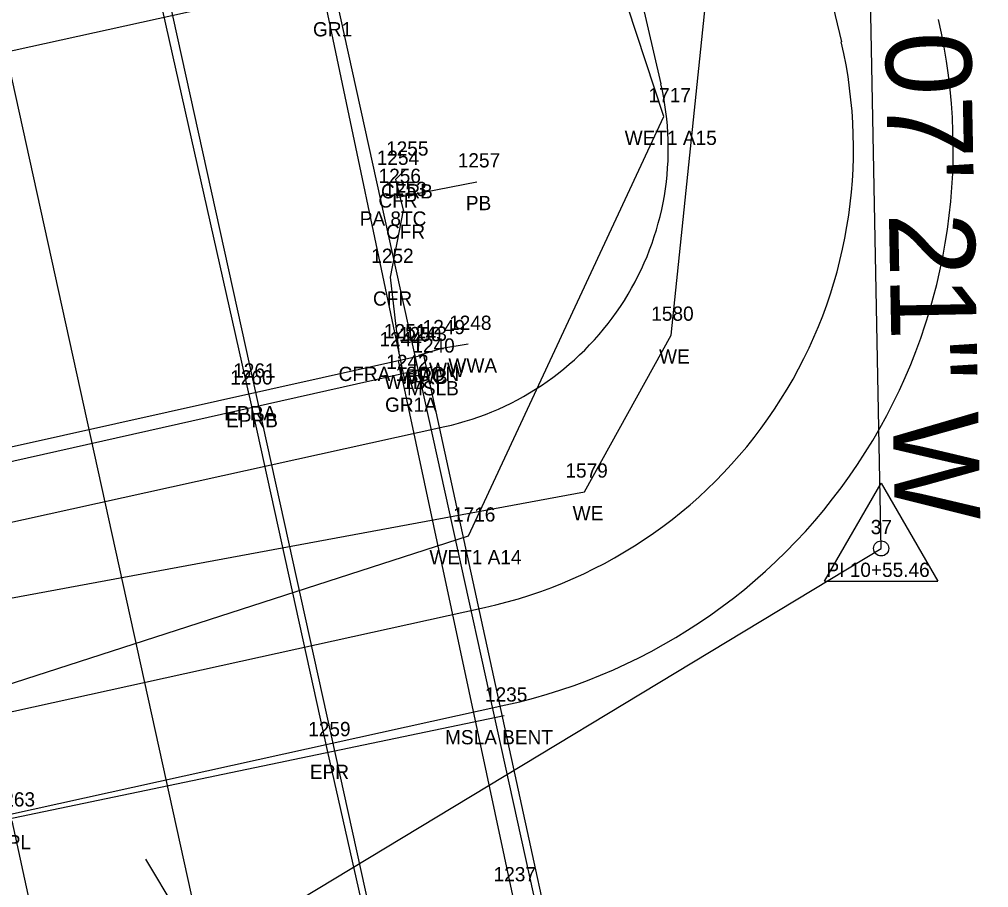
# Model space of a CAD drawing. Extents: x 2521558 to 2524785, y 882711 to 887632.
# Drawn here: x 2523776.7 to 2523844.7, y 885124.5 to 885185.4 of the extents above; entities that cross this region are included whole.
import ezdxf

# ---------------------------------------------------------------- set-up
doc = ezdxf.new("R2010")
doc.units = 0
for name, color, linetype in [('RD_EV_JW', 7, 'Continuous'), ('RD_EX_BldgApp', 7, 'Continuous'), ('RD_EX_BldgApp_txCode', 7, 'Continuous'), ('RD_EX_Bridge', 7, 'Continuous'), ('RD_EX_Bridge_txCode', 7, 'Continuous'), ('RD_EX_Conc', 7, 'Continuous'), ('RD_EX_Conc_txCode', 7, 'Continuous'), ('RD_EX_DR_Pipe', 7, 'Continuous'), ('RD_EX_DR_Pipe_txCode', 7, 'Continuous'), ('RD_EX_GuardRail', 7, 'Continuous'), ('RD_EX_GuardRail_txCode', 7, 'Continuous'), ('RD_EX_H2O', 7, 'Continuous'), ('RD_EX_H2O_txCode', 7, 'Continuous'), ('RD_EX_H2O_WetLd_txCode', 7, 'Continuous'), ('RD_EX_Misc', 7, 'Continuous'), ('RD_EX_Misc_txCode', 7, 'Continuous'), ('RD_EX_Road', 7, 'Continuous'), ('RD_EX_Road_txCode', 7, 'Continuous'), ('RD_HC_Cl', 7, 'Continuous'), ('RD_HC_Data', 7, 'Continuous'), ('RD_HC_Data_Tic', 7, 'Continuous'), ('RD_HC_txCode', 7, 'Continuous'), ('RD_PD_BCA', 7, 'Continuous'), ('RD_PD_Bridge', 7, 'Continuous'), ('RD_PD_CstnLmt', 7, 'Continuous'), ('RD_PD_DR_ErosCtrl', 7, 'Continuous'), ('RD_PD_Final_TrvlWay', 7, 'Continuous'), ('RD_SMD_Locator', 7, 'Continuous')]:
    doc.layers.add(name, color=color, linetype=linetype)

msp = doc.modelspace()

# ---------------------------------------------------------------- linework, layer by layer
at = {"layer": 'RD_EV_JW'}
msp.add_lwpolyline([(2523761.167, 885134.03), (2523808.209, 885149.207), (2523821.914, 885178.637), (2523802.851, 885236.548), (2523777.81, 885305.562), (2523748.196, 885444.322), (2523730.68, 885516.876), (2523708.637, 885617.3), (2523698.714, 885662.019), (2523727.827, 885665.815), (2523757.297, 885671.751)], dxfattribs=at)
at = {"layer": 'RD_EX_BldgApp'}
msp.add_lwpolyline([(2523819.439, 885087.441), (2523811.319, 885123.961), (2523803.308, 885161.503)], dxfattribs=at)
at = {"layer": 'RD_EX_Bridge'}
for points in [[(2523808.195, 885162.657), (2523806.339, 885162.355), (2523804.708, 885161.862)], [(2523774.906, 885077.596), (2523821.197, 885087.829), (2523805.064, 885161.895), (2523758.145, 885151.437), (2523774.906, 885077.596)]]:
    msp.add_lwpolyline(points, dxfattribs=at)
at = {"layer": 'RD_EX_Conc'}
msp.add_lwpolyline([(2523803.338, 885162.07), (2523802.732, 885167.359), (2523803.647, 885172.05), (2523803.117, 885174.241), (2523803.77, 885174.887)], dxfattribs=at)
at = {"layer": 'RD_EX_DR_Pipe'}
msp.add_line((2523803.266, 885172.973), (2523808.803, 885174.059), dxfattribs=at)
at = {"layer": 'RD_EX_GuardRail'}
msp.add_lwpolyline([(2523803.786, 885159.912), (2523798.239, 885186.256), (2523787.795, 885236.892)], dxfattribs=at)
at = {"layer": 'RD_EX_H2O'}
msp.add_lwpolyline([(2523738.909, 885147.498), (2523743.695, 885138.843), (2523816.359, 885152.29), (2523822.427, 885163.299), (2523826.928, 885206.612)], dxfattribs=at)
at = {"layer": 'RD_EX_Misc'}
for p, q in [((2523758.452, 885150.465), (2523805.656, 885161.063)), ((2523810.713, 885136.574), (2523763.829, 885126.803))]:
    msp.add_line(p, q, dxfattribs=at)
at = {"layer": 'RD_EX_Road'}
for p, q in [((2523792.777, 885159.311), (2523771.239, 885254.787)), ((2523792.894, 885158.826), (2523792.777, 885159.311)), ((2523798.302, 885134.145), (2523792.894, 885158.826)), ((2523803.791, 885109.941), (2523798.302, 885134.145)), ((2523781.516, 885104.768), (2523776.178, 885129.21))]:
    msp.add_line(p, q, dxfattribs=at)
at = {"layer": 'RD_HC_Cl'}
for p, q in [((2523641.165, 885794.201), (2524197.759, 883266.557)), ((2523837.18, 885148.323), (2523836.106, 885203.1)), ((2523672.044, 885048.634), (2523837.18, 885148.323))]:
    msp.add_line(p, q, dxfattribs=at)
at = {"layer": 'RD_HC_Data'}
for p, q in [((2523833.209, 885146.03), (2523837.181, 885152.909)), ((2523837.181, 885152.909), (2523841.149, 885146.03)), ((2523833.209, 885146.03), (2523841.149, 885146.03))]:
    msp.add_line(p, q, dxfattribs=at)
msp.add_circle((2523837.18, 885148.323), 0.529, dxfattribs=at)
at = {"layer": 'RD_HC_Data_Tic'}
msp.add_line((2523789.692, 885119.656), (2523785.558, 885126.504), dxfattribs=at)
at = {"layer": 'RD_PD_BCA'}
msp.add_lwpolyline([(2523762.054, 885126.595), (2523810.84, 885137.338)], dxfattribs=at)
msp.add_arc((2523802.238, 885176.402), 40, 282.41848, 13.07237, dxfattribs=at)
at = {"layer": 'RD_PD_Bridge'}
for points in [[(2523798.673, 885188.194), (2523752.772, 885178.086)], [(2523826.629, 885061.235), (2523798.673, 885188.194)]]:
    msp.add_lwpolyline(points, dxfattribs=at)
at = {"layer": 'RD_PD_CstnLmt'}
msp.add_line((2523810.511, 885229.196), (2523821.719, 885180.926), dxfattribs=at)
msp.add_lwpolyline([(2523757.753, 885146.127), (2523806.539, 885156.87)], dxfattribs=at)
msp.add_arc((2523802.238, 885176.402), 20, 282.41848, 13.07237, dxfattribs=at)
at = {"layer": 'RD_PD_DR_ErosCtrl'}
msp.add_line((2523823.174, 885232.137), (2523834.383, 885183.866), dxfattribs=at)
msp.add_lwpolyline([(2523760.548, 885133.431), (2523809.334, 885144.174)], dxfattribs=at)
msp.add_arc((2523802.238, 885176.402), 33, 282.41848, 13.07237, dxfattribs=at)
at = {"layer": 'RD_PD_Final_TrvlWay'}
msp.add_line((2523741.744, 885393.246), (2524015.933, 884148.078), dxfattribs=at)
at = {"layer": 'RD_SMD_Locator'}
for centre in [(2523821.914, 885178.637), (2523803.77, 885174.887), (2523803.117, 885174.241), (2523808.803, 885174.059), (2523803.266, 885172.973), (2523803.647, 885172.05), (2523802.732, 885167.359), (2523822.427, 885163.299), (2523806.339, 885162.355), (2523808.195, 885162.657), (2523803.338, 885162.07), (2523804.708, 885161.862), (2523805.064, 885161.895), (2523803.308, 885161.503), (2523805.656, 885161.063), (2523803.786, 885159.912), (2523792.777, 885159.311), (2523792.894, 885158.826), (2523816.359, 885152.29), (2523808.209, 885149.207), (2523837.18, 885148.323), (2523810.713, 885136.574), (2523798.302, 885134.145)]:
    msp.add_circle(centre, 0.001, dxfattribs=at)

# ---------------------------------------------------------------- texts
at = {"layer": 'RD_EX_BldgApp_txCode'}
for s, p in [('1244', (2523801.961, 885162.503)), ('W1B', (2523802.3, 885159.503)), ('1237', (2523809.973, 885124.961))]:
    msp.add_text(s, height=1, dxfattribs=at).set_placement(p)
at = {"layer": 'RD_EX_Bridge_txCode'}
for s, p in [('1249', (2523804.993, 885163.355)), ('1248', (2523806.848, 885163.657)), ('1250', (2523803.323, 885162.862)), ('1243', (2523803.718, 885162.895)), ('WWA', (2523806.801, 885160.657)), ('WWB', (2523803.33, 885159.862)), ('BRC', (2523803.812, 885159.895)), ('WW', (2523805.434, 885160.355))]:
    msp.add_text(s, height=1, dxfattribs=at).set_placement(p)
at = {"layer": 'RD_EX_Conc_txCode'}
for s, p in [('1255', (2523802.423, 885175.887)), ('1254', (2523801.77, 885175.241)), ('CFRB', (2523802.069, 885172.887)), ('1253', (2523802.301, 885173.05)), ('CFR', (2523801.888, 885172.241)), ('CFR', (2523802.419, 885170.05)), ('1252', (2523801.386, 885168.359)), ('CFR', (2523801.504, 885165.359)), ('1251', (2523802.275, 885163.07)), ('CFRA 18CON', (2523799.086, 885160.07))]:
    msp.add_text(s, height=1, dxfattribs=at).set_placement(p)
at = {"layer": 'RD_EX_DR_Pipe_txCode'}
for s, p in [('1257', (2523807.457, 885175.059)), ('1256', (2523801.896, 885173.973)), ('PB', (2523808.024, 885172.059)), ('PA 8TC', (2523800.573, 885170.973))]:
    msp.add_text(s, height=1, dxfattribs=at).set_placement(p)
at = {"layer": 'RD_EX_GuardRail_txCode'}
for s, p in [('GR1', (2523797.294, 885184.256)), ('1242', (2523802.439, 885160.912)), ('GR1A', (2523802.353, 885157.912))]:
    msp.add_text(s, height=1, dxfattribs=at).set_placement(p)
at = {"layer": 'RD_EX_H2O_txCode'}
for s, p in [('1580', (2523821.041, 885164.299)), ('WE', (2523821.588, 885161.299)), ('1579', (2523815.013, 885153.29)), ('WE', (2523815.521, 885150.29))]:
    msp.add_text(s, height=1, dxfattribs=at).set_placement(p)
at = {"layer": 'RD_EX_H2O_WetLd_txCode'}
for s, p in [('1717', (2523820.851, 885179.637)), ('WET1 A15', (2523819.174, 885176.637)), ('1716', (2523807.123, 885150.207)), ('WET1 A14', (2523805.469, 885147.207))]:
    msp.add_text(s, height=1, dxfattribs=at).set_placement(p)
at = {"layer": 'RD_EX_Misc_txCode'}
for s, p in [('1240', (2523804.27, 885162.063)), ('MSLB', (2523803.892, 885159.063)), ('1235', (2523809.366, 885137.574)), ('MSLA BENT', (2523806.563, 885134.574))]:
    msp.add_text(s, height=1, dxfattribs=at).set_placement(p)
at = {"layer": 'RD_EX_Road_txCode'}
for s, p in [('1260', (2523791.484, 885159.826)), ('1261', (2523791.691, 885160.311)), ('EPRA', (2523791.061, 885157.311)), ('EPRB', (2523791.193, 885156.826)), ('1259', (2523796.956, 885135.145)), ('EPR', (2523797.074, 885132.145)), ('1263', (2523774.808, 885130.21)), ('EPL', (2523774.974, 885127.21))]:
    msp.add_text(s, height=1, dxfattribs=at).set_placement(p)
at = {"layer": 'RD_HC_Data'}
msp.add_text('N 1%%d 07\' 21" W', height=6, rotation=271.12261, dxfattribs=at).set_placement((2523837.119, 885202.44))
at = {"layer": 'RD_HC_txCode'}
for s, p in [('37', (2523836.447, 885149.323)), ('PI 10+55.46', (2523833.337, 885146.323))]:
    msp.add_text(s, height=1, dxfattribs=at).set_placement(p)

doc.saveas('drawing.dxf')
